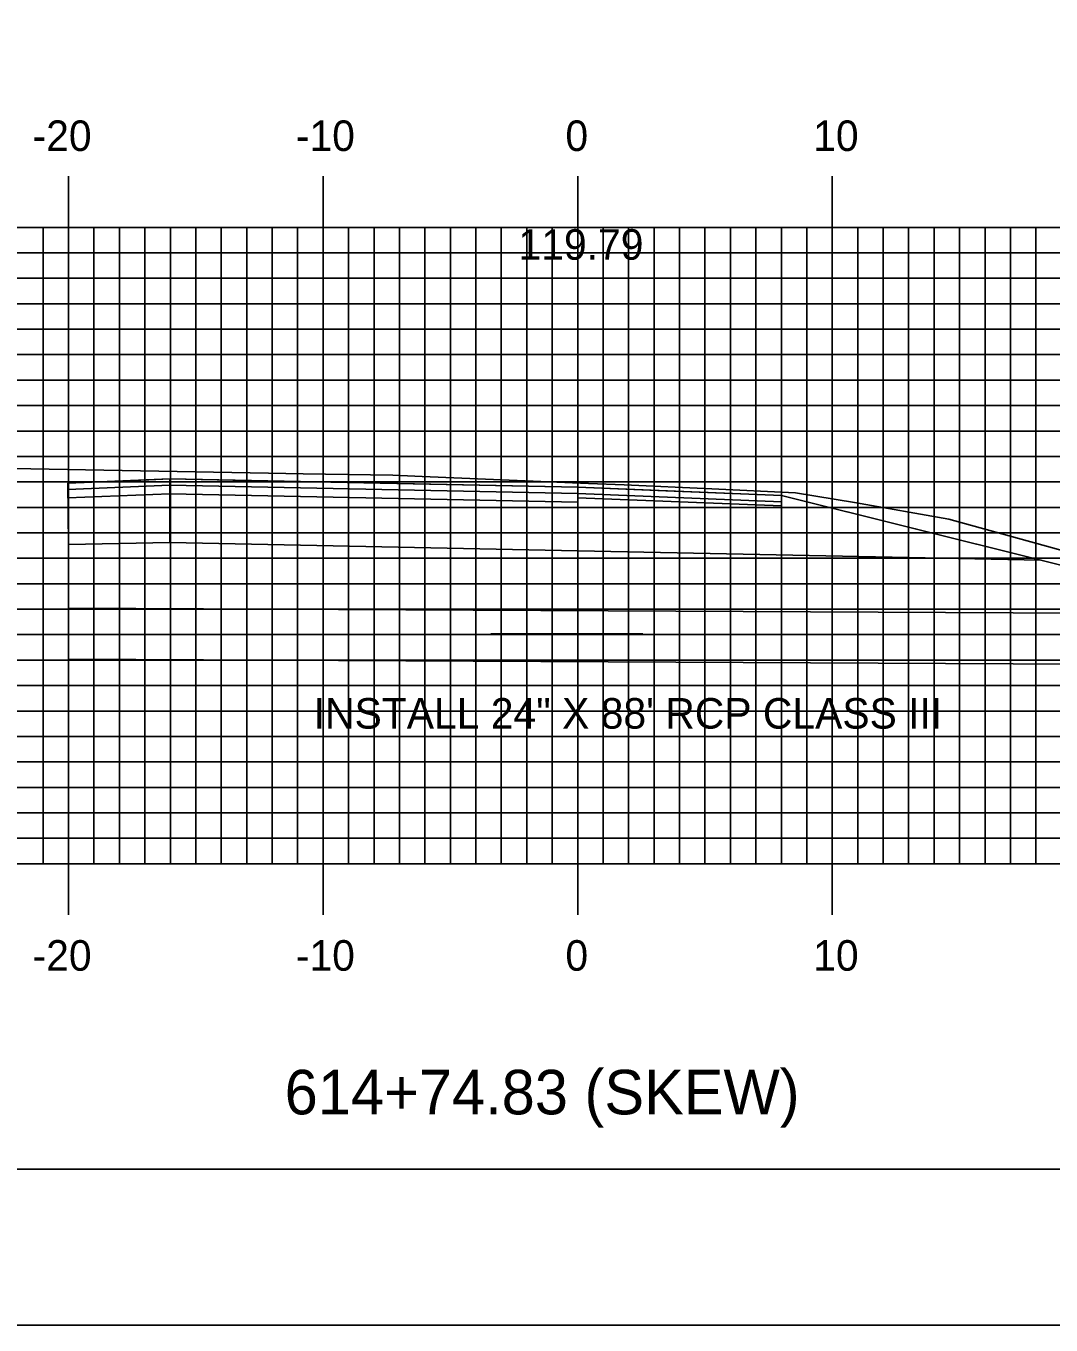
# Model space of a CAD drawing. Extents: x 844536 to 844879, y 363538 to 363758.
# Drawn here: x 844680.3 to 844720.6, y 363537.6 to 363588.6 of the extents above; entities that cross this region are included whole.
import ezdxf

# ---------------------------------------------------------------- set-up
doc = ezdxf.new("R2010")
doc.units = 0
for name, color, linetype in [('BORDER', 7, 'Continuous'), ('D_Drainage_Culvert', 7, 'Continuous'), ('D_Drainage_Text', 7, 'Continuous'), ('D_Roadway_Centerline', 7, 'Continuous'), ('D_Roadway_Centerline_Text', 7, 'Continuous'), ('D_Roadway_Edge_Shoulder', 7, 'Continuous'), ('D_Roadway_Edge_TW', 7, 'Continuous'), ('D_Roadway_FinishedGrade', 7, 'Continuous'), ('D_Roadway_Pavement', 7, 'Continuous'), ('D_Roadway_SubGrade', 7, 'Continuous'), ('H_V ANNOTATION', 7, 'Continuous'), ('MAJOR', 7, 'Continuous'), ('MINOR', 7, 'Continuous'), ('PLOT BOUNDARY', 7, 'Continuous'), ('S_Roadway_Centerline', 7, 'Continuous')]:
    doc.layers.add(name, color=color, linetype=linetype)

msp = doc.modelspace()

# ---------------------------------------------------------------- linework, layer by layer
at = {"layer": 'BORDER'}
msp.add_lwpolyline([(844552.364, 363543.721), (844872.364, 363543.721), (844872.364, 363753.721), (844552.364, 363753.721)], close=True, dxfattribs=at)
at = {"layer": 'D_Drainage_Culvert'}
for p, q in [((844681.964, 363565.76), (844729.235, 363565.523)), ((844698.548, 363564.749), (844704.518, 363564.749)), ((844681.964, 363563.76), (844729.235, 363563.523))]:
    msp.add_line(p, q, dxfattribs=at)
at = {"layer": 'D_Roadway_Centerline'}
msp.add_lwpolyline([(844681.94, 363570.677), (844681.94, 363570.677), (844685.115, 363570.804), (844685.945, 363570.837), (844689.031, 363570.775), (844701.964, 363570.514), (844705.428, 363570.375), (844708.685, 363570.245), (844709.973, 363570.193), (844715.225, 363568.881), (844720.16, 363567.648)], dxfattribs=at)
at = {"layer": 'D_Roadway_Edge_Shoulder'}
for points in [[(844685.945, 363570.837), (844681.94, 363570.677), (844681.94, 363570.427), (844685.945, 363570.587)], [(844701.964, 363570.514), (844709.973, 363570.193), (844709.973, 363569.943), (844701.964, 363570.264)]]:
    msp.add_lwpolyline(points, close=True, dxfattribs=at)
at = {"layer": 'D_Roadway_Edge_TW'}
msp.add_lwpolyline([(844685.945, 363570.837), (844701.964, 363570.514), (844701.964, 363570.264), (844685.945, 363570.587)], close=True, dxfattribs=at)
at = {"layer": 'D_Roadway_FinishedGrade'}
msp.add_lwpolyline([(844720.16, 363567.648), (844721.819, 363567.233)], dxfattribs=at)
at = {"layer": 'D_Roadway_Pavement'}
for points in [[(844685.945, 363570.587), (844681.94, 363570.427), (844681.94, 363570.094), (844685.945, 363570.253)], [(844685.945, 363570.587), (844701.964, 363570.264), (844701.964, 363569.931), (844685.945, 363570.253)], [(844701.964, 363570.264), (844709.973, 363569.943), (844709.973, 363569.776), (844701.964, 363570.098)]]:
    msp.add_lwpolyline(points, close=True, dxfattribs=at)
msp.add_lwpolyline([(844701.964, 363570.264), (844701.964, 363569.931)], dxfattribs=at)
msp.add_lwpolyline([(844701.964, 363570.264), (844701.964, 363569.931)], dxfattribs=at)
at = {"layer": 'D_Roadway_SubGrade'}
msp.add_line((844681.964, 363579.355), (844681.964, 363563.721), dxfattribs=at)
for points in [[(844685.945, 363570.253), (844681.94, 363570.094), (844681.94, 363570.427), (844681.94, 363570.677), (844681.964, 363568.258), (844685.945, 363568.337)], [(844685.945, 363570.253), (844701.964, 363569.931), (844701.964, 363568.014), (844685.945, 363568.337)], [(844701.964, 363569.931), (844701.964, 363570.264), (844709.973, 363569.943), (844709.973, 363570.193), (844720.16, 363567.648), (844701.964, 363568.014)]]:
    msp.add_lwpolyline(points, close=True, dxfattribs=at)
at = {"layer": 'MAJOR'}
for p, q in [((844681.964, 363582.725), (844681.964, 363580.721)), ((844691.964, 363582.725), (844691.964, 363580.721)), ((844701.964, 363582.725), (844701.964, 363580.721)), ((844711.964, 363582.725), (844711.964, 363580.721)), ((844561.964, 363580.721), (844841.964, 363580.721)), ((844561.964, 363580.721), (844841.964, 363580.721)), ((844681.964, 363555.721), (844681.964, 363580.721)), ((844691.964, 363555.721), (844691.964, 363580.721)), ((844701.964, 363555.721), (844701.964, 363580.721)), ((844711.964, 363555.721), (844711.964, 363580.721)), ((844561.964, 363575.721), (844841.964, 363575.721)), ((844561.964, 363570.721), (844841.964, 363570.721)), ((844561.964, 363565.721), (844841.964, 363565.721)), ((844561.964, 363560.721), (844841.964, 363560.721)), ((844561.964, 363555.721), (844841.964, 363555.721)), ((844561.964, 363555.721), (844841.964, 363555.721)), ((844681.964, 363553.717), (844681.964, 363555.721)), ((844691.964, 363553.717), (844691.964, 363555.721)), ((844701.964, 363553.717), (844701.964, 363555.721)), ((844711.964, 363553.717), (844711.964, 363555.721))]:
    msp.add_line(p, q, dxfattribs=at)
at = {"layer": 'MINOR'}
for p, q in [((844680.964, 363555.721), (844680.964, 363580.721)), ((844682.964, 363555.721), (844682.964, 363580.721)), ((844683.964, 363555.721), (844683.964, 363580.721)), ((844684.964, 363555.721), (844684.964, 363580.721)), ((844685.964, 363555.721), (844685.964, 363580.721)), ((844686.964, 363555.721), (844686.964, 363580.721)), ((844687.964, 363555.721), (844687.964, 363580.721)), ((844688.964, 363555.721), (844688.964, 363580.721)), ((844689.964, 363555.721), (844689.964, 363580.721)), ((844690.964, 363555.721), (844690.964, 363580.721)), ((844692.964, 363555.721), (844692.964, 363580.721)), ((844693.964, 363555.721), (844693.964, 363580.721)), ((844694.964, 363555.721), (844694.964, 363580.721)), ((844695.964, 363555.721), (844695.964, 363580.721)), ((844696.964, 363555.721), (844696.964, 363580.721)), ((844697.964, 363555.721), (844697.964, 363580.721)), ((844698.964, 363555.721), (844698.964, 363580.721)), ((844699.964, 363555.721), (844699.964, 363580.721)), ((844700.964, 363555.721), (844700.964, 363580.721)), ((844702.964, 363555.721), (844702.964, 363580.721)), ((844703.964, 363555.721), (844703.964, 363580.721)), ((844704.964, 363555.721), (844704.964, 363580.721)), ((844705.964, 363555.721), (844705.964, 363580.721)), ((844706.964, 363555.721), (844706.964, 363580.721)), ((844707.964, 363555.721), (844707.964, 363580.721)), ((844708.964, 363555.721), (844708.964, 363580.721)), ((844709.964, 363555.721), (844709.964, 363580.721)), ((844710.964, 363555.721), (844710.964, 363580.721)), ((844712.964, 363555.721), (844712.964, 363580.721)), ((844713.964, 363555.721), (844713.964, 363580.721)), ((844714.964, 363555.721), (844714.964, 363580.721)), ((844715.964, 363555.721), (844715.964, 363580.721)), ((844716.964, 363555.721), (844716.964, 363580.721)), ((844717.964, 363555.721), (844717.964, 363580.721)), ((844718.964, 363555.721), (844718.964, 363580.721)), ((844719.964, 363555.721), (844719.964, 363580.721)), ((844561.964, 363579.721), (844841.964, 363579.721)), ((844561.964, 363578.721), (844841.964, 363578.721)), ((844561.964, 363577.721), (844841.964, 363577.721)), ((844561.964, 363576.721), (844841.964, 363576.721)), ((844561.964, 363574.721), (844841.964, 363574.721)), ((844561.964, 363573.721), (844841.964, 363573.721)), ((844561.964, 363572.721), (844841.964, 363572.721)), ((844561.964, 363571.721), (844841.964, 363571.721)), ((844561.964, 363569.721), (844841.964, 363569.721)), ((844561.964, 363568.721), (844841.964, 363568.721)), ((844561.964, 363567.721), (844841.964, 363567.721)), ((844561.964, 363566.721), (844841.964, 363566.721)), ((844561.964, 363564.721), (844841.964, 363564.721)), ((844561.964, 363563.721), (844841.964, 363563.721)), ((844561.964, 363562.721), (844841.964, 363562.721)), ((844561.964, 363561.721), (844841.964, 363561.721)), ((844561.964, 363559.721), (844841.964, 363559.721)), ((844561.964, 363558.721), (844841.964, 363558.721)), ((844561.964, 363557.721), (844841.964, 363557.721)), ((844561.964, 363556.721), (844841.964, 363556.721))]:
    msp.add_line(p, q, dxfattribs=at)
at = {"layer": 'PLOT BOUNDARY'}
msp.add_lwpolyline([(844536.177, 363537.603), (844876.177, 363537.603), (844876.177, 363757.603), (844536.177, 363757.603)], close=True, dxfattribs=at)
at = {"layer": 'S_Roadway_Centerline'}
msp.add_lwpolyline([(844679.76, 363571.247), (844689.824, 363571.067), (844691.179, 363571.043), (844694.707, 363570.986), (844695.857, 363570.928), (844702.39, 363570.664), (844703.787, 363570.607), (844707.233, 363570.456), (844710.519, 363570.29), (844712.84, 363569.909), (844716.548, 363569.258), (844728.995, 363565.816), (844729.346, 363565.729), (844729.529, 363565.673), (844729.779, 363565.639), (844742.705, 363563.262), (844744.336, 363563.196), (844747.804, 363563.646)], dxfattribs=at)

# ---------------------------------------------------------------- texts
at = {"layer": 'D_Drainage_Text'}
msp.add_text('INSTALL 24" X 88\' RCP CLASS III', height=1.2, dxfattribs=at).set_placement((844691.594, 363561.03))
at = {"layer": 'D_Roadway_Centerline_Text'}
msp.add_text('119.79', height=1.2, dxfattribs=at).set_placement((844699.641, 363579.449))
at = {"layer": 'H_V ANNOTATION'}
for s, height, p in [('-20', 1.2, (844680.551, 363583.721)), ('-10', 1.2, (844690.893, 363583.721)), ('0', 1.2, (844701.482, 363583.721)), ('10', 1.2, (844711.214, 363583.721)), ('-20', 1.2, (844680.551, 363551.521)), ('-10', 1.2, (844690.893, 363551.521)), ('0', 1.2, (844701.482, 363551.521)), ('10', 1.2, (844711.214, 363551.521)), ('614+74.83 (SKEW)', 1.74996, (844690.454, 363545.877))]:
    msp.add_text(s, height=height, dxfattribs=at).set_placement(p)

doc.saveas('drawing.dxf')
